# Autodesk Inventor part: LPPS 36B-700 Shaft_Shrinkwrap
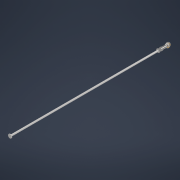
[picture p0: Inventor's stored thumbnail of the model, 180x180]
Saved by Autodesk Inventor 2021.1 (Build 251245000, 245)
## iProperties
Created: 2020-09
Part Number: LPPS 36B-700 Shaft_Shrinkwrap
Material: Generic
Document SubType Name: Modeling
Designer: J. Nielson
Density: 1 g/cm^3
Appearance: Default
Author: J. Nielson
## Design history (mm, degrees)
derived "LPPS 36B-700.iam"
body "Solid1"
node "LPPS-36B-700 ROD.ipt:1"
node "Custom Flanged Nut.ipt:1"
body "Solid2"
node "FEMALE Rod End SW.ipt:1"
body "Solid3"
node "JIS B 1181 - M8x1(4).ipt:1"
body "Solid4"
